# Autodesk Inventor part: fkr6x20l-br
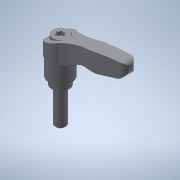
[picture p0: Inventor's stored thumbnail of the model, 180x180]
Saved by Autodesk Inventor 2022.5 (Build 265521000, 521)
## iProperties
Created: 2017-09
Part Number: fkr6x20l-br
Material: 一般
Document SubType Name: Modeling
Designer: imaocorp
Density: 1 g/cm^3
Appearance: 既定
Author: imaocorp
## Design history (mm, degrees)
node "fkr6x20l-br.x_t1"
node "fkr6x20l-br"
node "Base1"
